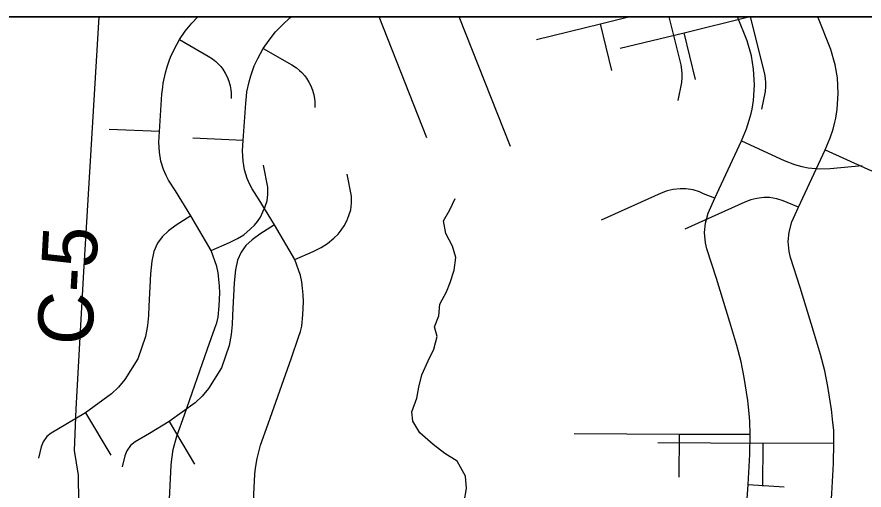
# Model space of a CAD drawing. Extents: x -38.2 to 41.9, y -4 to 24.9.
# Drawn here: x 4.114 to 4.989, y 20.411 to 20.9 of the extents above; entities that cross this region are included whole.
import ezdxf

# ---------------------------------------------------------------- set-up
doc = ezdxf.new("R2010")
doc.units = 0
for name, color, linetype in [('GM_X_County_Road_Text', 7, 'Continuous'), ('GM_X_Interchange_Ramps', 7, 'Continuous'), ('GM_X_Minor_River', 7, 'Continuous'), ('GM_X_State_Location', 7, 'Continuous'), ('GM_X_Township_Road', 7, 'Continuous'), ('GM_X_Township_Road_Text', 7, 'Continuous'), ('SH_Cut_Line', 7, 'Continuous'), ('SH_Data', 7, 'Continuous')]:
    doc.layers.add(name, color=color, linetype=linetype)

msp = doc.modelspace()

# ---------------------------------------------------------------- linework, layer by layer
at = {"layer": 'GM_X_Interchange_Ramps'}
for points in [[(5.01828, 19.2401), (5.08694, 20.33209), (5.12429, 20.9), (2.11034, 20.9), (2.11244, 20.45264), (2.1223, 20.27254), (2.13391, 19.39602)], [(5.10476, 19.23091), (5.17341, 20.32291), (5.21137, 20.9), (2.19678, 20.9), (2.19891, 20.44345), (2.20877, 20.26335), (2.22039, 19.38683)]]:
    msp.add_lwpolyline(points, dxfattribs=at)
at = {"layer": 'GM_X_Minor_River'}
msp.add_lwpolyline([(4.57593, 20.39909), (4.57824, 20.41274), (4.57714, 20.42564), (4.56883, 20.44121), (4.55595, 20.44922), (4.54383, 20.45836), (4.5302, 20.47054), (4.52302, 20.48231), (4.52191, 20.49218), (4.52688, 20.5062), (4.52919, 20.51758), (4.53227, 20.53047), (4.53876, 20.54487), (4.54449, 20.55699), (4.54795, 20.56988), (4.54532, 20.57975), (4.5499, 20.59112), (4.5507, 20.60326), (4.55757, 20.61614), (4.56139, 20.62561), (4.56561, 20.6385), (4.56716, 20.6514), (4.56378, 20.66317), (4.55698, 20.67647), (4.55474, 20.68938), (4.56123, 20.70074), (4.56657, 20.71249)], dxfattribs=at)
at = {"layer": 'GM_X_State_Location'}
for p, q in [((4.62397, 20.76605), (4.57078, 20.9)), ((4.81494, 20.83533), (4.80314, 20.88373)), ((4.34766, 20.77252), (4.29561, 20.77465)), ((4.27124, 20.48203), (4.29737, 20.43808)), ((4.88447, 20.41526), (4.88499, 20.45951))]:
    msp.add_line(p, q, dxfattribs=at)
for points in [[(4.35646, 20.36482), (4.35978, 20.42767), (4.36032, 20.43406), (4.36188, 20.44404), (4.36552, 20.4577), (4.37328, 20.47974), (4.39736, 20.54796), (4.40486, 20.56924), (4.4067, 20.57491), (4.40823, 20.58066), (4.40937, 20.59223), (4.41003, 20.60567), (4.4097, 20.61289), (4.40904, 20.61993), (4.40822, 20.62648), (4.40675, 20.63288), (4.40087, 20.64947), (4.38007, 20.68535), (4.3641, 20.71114), (4.35678, 20.72231), (4.35433, 20.72699), (4.35173, 20.73307), (4.34902, 20.74191), (4.34742, 20.75103), (4.34699, 20.7616), (4.34766, 20.77252), (4.35018, 20.81099), (4.35088, 20.81828), (4.35149, 20.82254), (4.35368, 20.83307), (4.35543, 20.83928), (4.35751, 20.84538), (4.35908, 20.84939), (4.36263, 20.85723), (4.36828, 20.86741), (4.37427, 20.87615), (4.38108, 20.88446), (4.38859, 20.89214), (4.39588, 20.89893), (4.3973, 20.9)], [(4.73699, 20.8676), (4.80314, 20.88373), (4.86987, 20.9)], [(4.88363, 20.80463), (4.88729, 20.82316), (4.88776, 20.8281), (4.88775, 20.83222), (4.88738, 20.83634), (4.88646, 20.8413), (4.87191, 20.9)], [(4.95596, 20.49131), (4.95561, 20.49467), (4.95185, 20.51834), (4.94851, 20.5345), (4.94416, 20.55128), (4.93677, 20.57544), (4.92297, 20.62066), (4.91324, 20.65144), (4.9117, 20.65754), (4.91084, 20.66802), (4.91164, 20.67779), (4.91445, 20.6882), (4.92135, 20.70359), (4.94907, 20.76283), (4.95415, 20.77528), (4.95706, 20.78412), (4.95883, 20.79114), (4.95982, 20.79541), (4.96132, 20.80457), (4.96241, 20.82076), (4.96154, 20.83694), (4.95927, 20.85063), (4.95486, 20.86621), (4.9413, 20.9)], [(4.36828, 20.86741), (4.39801, 20.85039), (4.40252, 20.84742), (4.40574, 20.84482), (4.40814, 20.84254), (4.4109, 20.83947), (4.4129, 20.83685), (4.41556, 20.83268), (4.41743, 20.82901), (4.41924, 20.82442), (4.42055, 20.81966), (4.42125, 20.81561), (4.42155, 20.81234), (4.42163, 20.80905), (4.42153, 20.80659)], [(4.94907, 20.76283), (4.99308, 20.74265), (5.00358, 20.73835), (5.01125, 20.73626), (5.01799, 20.73489), (5.02927, 20.73379), (5.04055, 20.73412), (5.07369, 20.73721)], [(4.40087, 20.64947), (4.41993, 20.65788), (4.42829, 20.66197), (4.43471, 20.66586), (4.44113, 20.67149), (4.44559, 20.67577), (4.4487, 20.67966), (4.45201, 20.68414), (4.45454, 20.68938), (4.45687, 20.69502), (4.45881, 20.70086), (4.45959, 20.70747), (4.45958, 20.71486), (4.45516, 20.73754)], [(4.92135, 20.70359), (4.90969, 20.70822), (4.90548, 20.71001), (4.89904, 20.71206), (4.89148, 20.71336), (4.88565, 20.71336), (4.87841, 20.71255), (4.87216, 20.71108), (4.86584, 20.7087), (4.80396, 20.68075)], [(4.38007, 20.68535), (4.36475, 20.67559), (4.35673, 20.66988), (4.35031, 20.66382), (4.3455, 20.65705), (4.34176, 20.64866), (4.33962, 20.63868), (4.33838, 20.62549), (4.33651, 20.59188), (4.33616, 20.58226), (4.33527, 20.5721), (4.33313, 20.56068), (4.32517, 20.53758), (4.31189, 20.5163), (4.3053, 20.50837), (4.29795, 20.50139), (4.27124, 20.48203), (4.25072, 20.46983), (4.23582, 20.46093), (4.23117, 20.45744), (4.2273, 20.45183), (4.22517, 20.4466), (4.22246, 20.43517)], [(4.95069, 20.33407), (4.95583, 20.40771), (4.9575, 20.43877), (4.95793, 20.45964), (4.95773, 20.47323), (4.95703, 20.48124), (4.95596, 20.49131)], [(4.95793, 20.45964), (4.88499, 20.45951), (4.77619, 20.46022)]]:
    msp.add_lwpolyline(points, dxfattribs=at)
at = {"layer": 'GM_X_Township_Road'}
for p, q in [((4.53749, 20.77524), (4.48795, 20.9)), ((4.72846, 20.84452), (4.71666, 20.89292)), ((4.26118, 20.7817), (4.20913, 20.78384)), ((4.18476, 20.49122), (4.21089, 20.44727)), ((4.79799, 20.42445), (4.79851, 20.4687)), ((4.86935, 20.4169), (4.90655, 20.41473))]:
    msp.add_line(p, q, dxfattribs=at)
for points in [[(4.26999, 20.37401), (4.2733, 20.43686), (4.27385, 20.44324), (4.27541, 20.45323), (4.27905, 20.46689), (4.2868, 20.48893), (4.31088, 20.55715), (4.31839, 20.57843), (4.32022, 20.5841), (4.32175, 20.58985), (4.3229, 20.60142), (4.32355, 20.61486), (4.32322, 20.62207), (4.32256, 20.62911), (4.32174, 20.63567), (4.32027, 20.64206), (4.31439, 20.65865), (4.29359, 20.69454), (4.27762, 20.72033), (4.2703, 20.7315), (4.26785, 20.73618), (4.26525, 20.74226), (4.26254, 20.7511), (4.26095, 20.76022), (4.26052, 20.77079), (4.26118, 20.7817), (4.2637, 20.82018), (4.2644, 20.82747), (4.26502, 20.83173), (4.2672, 20.84226), (4.26896, 20.84846), (4.27104, 20.85457), (4.2726, 20.85858), (4.27615, 20.86642), (4.2818, 20.87659), (4.2878, 20.88534), (4.29461, 20.89365), (4.30081, 20.9)], [(4.65051, 20.87679), (4.71666, 20.89292), (4.74571, 20.9)], [(4.79716, 20.81382), (4.80082, 20.83235), (4.80128, 20.83729), (4.80128, 20.84141), (4.8009, 20.84553), (4.79998, 20.85048), (4.78771, 20.9)], [(4.86949, 20.5005), (4.86913, 20.50386), (4.86537, 20.52753), (4.86203, 20.54369), (4.85768, 20.56047), (4.8503, 20.58462), (4.83649, 20.62985), (4.82677, 20.66063), (4.82522, 20.66673), (4.82436, 20.67721), (4.82516, 20.68698), (4.82797, 20.69738), (4.83487, 20.71278), (4.86259, 20.77202), (4.86768, 20.78447), (4.87058, 20.79331), (4.87236, 20.80033), (4.87334, 20.8046), (4.87484, 20.81376), (4.87593, 20.82995), (4.87506, 20.84613), (4.87279, 20.85982), (4.86838, 20.8754), (4.85851, 20.9)], [(4.2818, 20.87659), (4.31153, 20.85957), (4.31604, 20.85661), (4.31926, 20.85401), (4.32166, 20.85173), (4.32442, 20.84866), (4.32643, 20.84604), (4.32909, 20.84187), (4.33095, 20.8382), (4.33276, 20.83361), (4.33407, 20.82885), (4.33477, 20.8248), (4.33508, 20.82153), (4.33515, 20.81824), (4.33506, 20.81577)], [(4.86259, 20.77202), (4.9066, 20.75184), (4.9171, 20.74754), (4.92477, 20.74545), (4.93151, 20.74407), (4.94279, 20.74297), (4.95407, 20.74331), (4.98721, 20.7464)], [(4.31439, 20.65865), (4.33345, 20.66707), (4.34182, 20.67116), (4.34823, 20.67505), (4.35465, 20.68068), (4.35912, 20.68496), (4.36222, 20.68885), (4.36553, 20.69333), (4.36806, 20.69857), (4.37039, 20.70421), (4.37233, 20.71005), (4.37311, 20.71666), (4.3731, 20.72405), (4.36869, 20.74673)], [(4.83487, 20.71278), (4.82322, 20.71741), (4.819, 20.7192), (4.81257, 20.72125), (4.805, 20.72255), (4.79917, 20.72255), (4.79193, 20.72174), (4.78569, 20.72027), (4.77936, 20.71789), (4.71748, 20.68993)], [(4.29359, 20.69454), (4.27827, 20.68478), (4.27025, 20.67907), (4.26384, 20.67301), (4.25902, 20.66624), (4.25528, 20.65785), (4.25314, 20.64787), (4.2519, 20.63468), (4.25003, 20.60107), (4.24968, 20.59145), (4.24879, 20.58129), (4.24665, 20.56987), (4.23869, 20.54677), (4.22541, 20.52549), (4.21882, 20.51755), (4.21147, 20.51058), (4.18476, 20.49122), (4.16424, 20.47902), (4.14934, 20.47012), (4.14469, 20.46663), (4.14082, 20.46102), (4.13869, 20.45579), (4.13598, 20.44436)], [(4.86421, 20.34326), (4.86935, 20.4169), (4.87102, 20.44796), (4.87145, 20.46883), (4.87126, 20.48242), (4.87055, 20.49043), (4.86949, 20.5005)], [(4.87145, 20.46883), (4.79851, 20.4687), (4.68972, 20.4694)]]:
    msp.add_lwpolyline(points, dxfattribs=at)
at = {"layer": 'GM_X_Township_Road_Text'}
msp.add_lwpolyline([(4.1777, 20.39866), (4.17745, 20.42675), (4.17326, 20.45205), (4.17499, 20.49507), (4.17922, 20.56938), (4.18277, 20.63685), (4.19886, 20.9)], dxfattribs=at)
at = {"layer": 'SH_Cut_Line'}
msp.add_lwpolyline([(8.9, 20.9), (2.11034, 20.9), (2.11244, 20.45264), (2.1223, 20.27254), (2.13391, 19.39602), (2.13802, 18.89762), (2.14208, 18.29522), (2.14295, 18.17094), (2.14266, 17.83804), (2.14219, 17.75625), (2.15214, 17.64161), (2.15488, 17.59725), (2.15692, 17.57038), (2.14864, 17.15564)], dxfattribs=at)
at = {"layer": 'SH_Data'}
msp.add_line((2.1, 20.9), (8.9, 20.9), dxfattribs=at)

# ---------------------------------------------------------------- texts
at = {"layer": 'GM_X_County_Road_Text'}
msp.add_text('C-5', height=0.056818, rotation=86.79999, dxfattribs=at).set_placement((4.19113, 20.55973))

doc.saveas('drawing.dxf')
